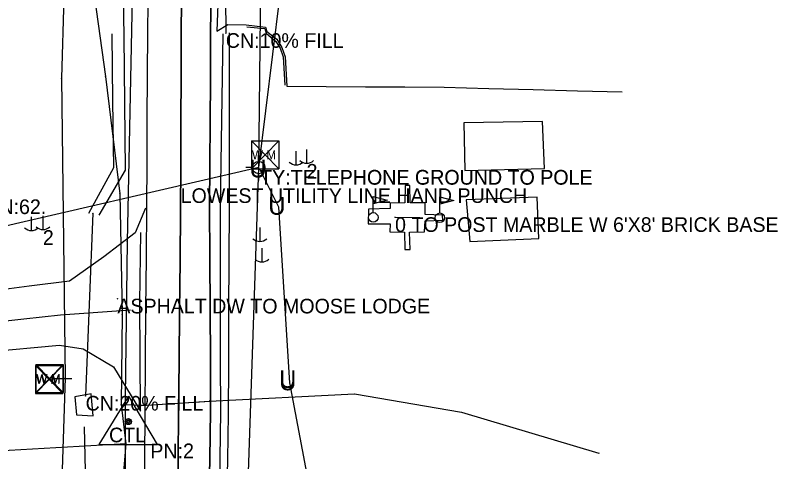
# Model space of a CAD drawing. Extents: x 1707085 to 1720058, y 548761 to 560063.
# Drawn here: x 1712426.8 to 1712686.7, y 550534.1 to 550686.5 of the extents above; entities that cross this region are included whole.
import ezdxf

# ---------------------------------------------------------------- set-up
doc = ezdxf.new("R2010")
doc.units = 0
for name, color, linetype in [('3', 7, 'Continuous'), ('44', 7, 'Continuous'), ('Default', 7, 'Continuous'), ('R_Contour Annot', 7, 'Continuous'), ('R_Horz Alg Annot', 7, 'Continuous'), ('R_Water Annot', 7, 'Continuous'), ('S_CURB', 7, 'Continuous'), ('S_DRG_PT_SYM', 7, 'Continuous'), ('S_DRIVEWAY', 7, 'Continuous'), ('S_EDGE_CONCRETE', 7, 'Continuous'), ('S_EDGE_PAVEMENT', 7, 'Continuous'), ('S_ELECTRIC_UTILITIES_ANNOT', 7, 'Continuous'), ('S_FLAG_POLE', 7, 'Continuous'), ('S_GAS_UTILITIES', 7, 'Continuous'), ('S_MSC_PT_SYM', 7, 'Continuous'), ('S_PAVEMENT_CROWN', 7, 'Continuous'), ('S_PRIMARY_CTL_ANNOT', 7, 'Continuous'), ('S_SIDE_DRAIN_ANNOT', 7, 'Continuous'), ('S_SIGN_ANNOT', 7, 'Continuous'), ('S_SURVEY_TEXT_ANNOT', 7, 'Continuous'), ('S_UNDERGROUND_CABLE', 7, 'Continuous'), ('S_UNDERGROUND_CABLE_ANNOT', 7, 'Continuous'), ('S_UTILITY_POLE', 7, 'Continuous'), ('S_UTILITY_POLE_ANNOT', 7, 'Continuous'), ('S_UTL_PT_SYM', 7, 'Continuous')]:
    doc.layers.add(name, color=color, linetype=linetype)

msp = doc.modelspace()

# ---------------------------------------------------------------- linework, layer by layer
for points in [[(1712463.94, 550855.4), (1712463.2, 550842.56), (1712462.46, 550829.72), (1712462.55, 550815.13), (1712462.64, 550800.54), (1712462.46, 550798.31), (1712462.44, 550791.97), (1712462.37, 550776.28), (1712462.3, 550760.58), (1712462.68, 550740.27), (1712463.06, 550719.96), (1712463.44, 550699.64), (1712463.81, 550679.33), (1712464.04, 550656.46), (1712464.27, 550633.6), (1712455.29, 550618.31)], [(1712499.77, 550680.44), (1712499.76, 550665.56), (1712499.74, 550650.67), (1712499.72, 550635.78), (1712499.71, 550620.89), (1712499.63, 550603.25), (1712499.55, 550585.61), (1712499.47, 550567.97), (1712499.4, 550550.32), (1712499.11, 550534.87), (1712498.82, 550519.41), (1712498.53, 550503.95), (1712498.24, 550488.49), (1712498.1, 550472.1), (1712497.96, 550455.71), (1712497.82, 550439.31), (1712497.69, 550422.92)], [(1712459.68, 550680.09), (1712459.99, 550657.24), (1712460.29, 550634.4), (1712451.79, 550618.84)], [(1712497.6, 550680.15), (1712497.36, 550665.48), (1712497.12, 550650.8), (1712496.87, 550636.13), (1712496.63, 550621.46), (1712496.66, 550603.89), (1712496.68, 550586.31), (1712496.71, 550568.74), (1712496.74, 550551.17), (1712496.57, 550535.35), (1712496.4, 550519.52), (1712496.23, 550503.7), (1712496.06, 550487.88), (1712496.27, 550471.69), (1712496.49, 550455.51), (1712496.71, 550439.33), (1712496.93, 550423.15)], [(1712450.26, 550546.06), (1712450.63, 550530.87), (1712451.01, 550515.67), (1712451.38, 550500.48), (1712451.76, 550485.28), (1712453.29, 550470.36), (1712454.82, 550455.43), (1712456.35, 550440.5), (1712457.89, 550425.57), (1712457.37, 550408.66), (1712456.85, 550391.74), (1712456.33, 550374.83), (1712455.82, 550357.92), (1712457.14, 550352.68), (1712454.4, 550340.57)]]:
    msp.add_lwpolyline(points)
msp.add_lwpolyline([(1712452.7, 550557.31), (1712447.08, 550556.32), (1712447.67, 550550.13), (1712453.36, 550549.82)], close=True)
at = {"layer": '3'}
for p, q in [((1712498.23, 550737.65), (1712498.59, 550680.34)), ((1712453.31, 550618.91), (1712450.79, 550556.58))]:
    msp.add_line(p, q, dxfattribs=at)
at = {"layer": '44'}
for p, q in [((1712468.97, 550809.65), (1712465.01, 550609.18)), ((1712465.01, 550609.18), (1712464.32, 550556.31)), ((1712464.32, 550556.31), (1712464.29, 550357.8))]:
    msp.add_line(p, q, dxfattribs=at)
at = {"layer": 'R_Contour Annot'}
for p, q in [((1712465.36, 550556.54), (1712455.33, 550540.02)), ((1712465.36, 550556.54), (1712475.19, 550540.02)), ((1712455.33, 550540.02), (1712475.19, 550540.02))]:
    msp.add_line(p, q, dxfattribs=at)
for radius in [1.04, 0.609, 0.344]:
    msp.add_circle((1712465.36, 550547.84), radius, dxfattribs=at)
at = {"layer": 'R_Horz Alg Annot'}
msp.add_line((1712556.28, 550617.54), (1712564.64, 550617.46), dxfattribs=at)
at = {"layer": 'R_Water Annot'}
for p, q in [((1712444.67, 550744.2), (1712442.63, 550664.98)), ((1712442.63, 550664.98), (1712443.82, 550562.74)), ((1712507.29, 550643.57), (1712516.63, 550643.57)), ((1712507.29, 550643.57), (1712507.29, 550634.08)), ((1712507.29, 550643.57), (1712516.63, 550634.08)), ((1712516.63, 550643.57), (1712507.29, 550634.08)), ((1712516.63, 550643.57), (1712516.63, 550634.08)), ((1712507.29, 550634.08), (1712516.63, 550634.08)), ((1712433.66, 550566.94), (1712443, 550566.94)), ((1712433.66, 550566.94), (1712433.66, 550557.45)), ((1712433.66, 550566.94), (1712443, 550557.45)), ((1712443, 550566.94), (1712433.66, 550557.45)), ((1712433.85, 550567.29), (1712443.19, 550567.29)), ((1712433.85, 550567.29), (1712433.85, 550557.79)), ((1712433.85, 550567.29), (1712443.19, 550557.79)), ((1712443.19, 550567.29), (1712433.85, 550557.79)), ((1712443, 550566.94), (1712443, 550557.45)), ((1712443.19, 550567.29), (1712443.19, 550557.79)), ((1712446.1, 550562.41), (1712439.34, 550562.47)), ((1712443.82, 550562.74), (1712442.13, 550508.33)), ((1712433.66, 550557.45), (1712443, 550557.45)), ((1712433.85, 550557.79), (1712443.19, 550557.79))]:
    msp.add_line(p, q, dxfattribs=at)
at = {"layer": 'S_CURB'}
msp.add_lwpolyline([(1712505.73, 550682.49), (1712511.84, 550681.96), (1712512.3, 550680.34), (1712515.58, 550677.49), (1712517.06, 550675.18), (1712518.1, 550672.22), (1712518.66, 550662.66)], dxfattribs=at)
at = {"layer": 'S_DRG_PT_SYM'}
for points in [[(1712498.59, 550680.34), (1712498.59, 550680.39), (1712498.59, 550680.34), (1712498.54, 550680.34), (1712498.59, 550680.34), (1712498.59, 550680.29), (1712498.59, 550680.34), (1712498.64, 550680.34)], [(1712453.31, 550618.91), (1712453.31, 550618.96), (1712453.31, 550618.91), (1712453.26, 550618.91), (1712453.31, 550618.91), (1712453.31, 550618.86), (1712453.31, 550618.91), (1712453.36, 550618.91)], [(1712450.79, 550556.58), (1712450.79, 550556.63), (1712450.79, 550556.58), (1712450.74, 550556.58), (1712450.79, 550556.58), (1712450.79, 550556.53), (1712450.79, 550556.58), (1712450.84, 550556.58)]]:
    msp.add_lwpolyline(points, dxfattribs=at)
at = {"layer": 'S_DRIVEWAY'}
msp.add_lwpolyline([(1712496.1, 550696.36), (1712495.51, 550681.07), (1712499.26, 550683.27), (1712505.5, 550683.16), (1712512.1, 550682.4), (1712512.62, 550680.93), (1712515.94, 550678.26), (1712517.66, 550675.48), (1712518.8, 550672.25), (1712519.38, 550662.3), (1712532.8, 550662.2), (1712546.21, 550662.09), (1712559.63, 550661.99), (1712573.04, 550661.89), (1712588.2, 550661.49), (1712603.36, 550661.09), (1712618.51, 550660.69), (1712633.67, 550660.29)], dxfattribs=at)
at = {"layer": 'S_EDGE_CONCRETE'}
for points in [[(1712606.51, 550650.18), (1712593.1, 550649.98), (1712579.68, 550649.78), (1712580.01, 550633.53), (1712593.6, 550633.84), (1712607.19, 550634.15)], [(1712572.51, 550616.5), (1712572.44, 550618.29), (1712566.54, 550618.47), (1712566.54, 550622.44), (1712561.41, 550622.48), (1712561.32, 550628.41), (1712559.67, 550628.42), (1712559.62, 550622.44), (1712554.59, 550622.31), (1712554.57, 550620.48), (1712547.23, 550620.33), (1712547.15, 550615.25), (1712554.58, 550615.35), (1712554.51, 550612.52), (1712559.51, 550612.4), (1712559.66, 550606.51), (1712561.46, 550606.52), (1712561.25, 550612.43), (1712566.33, 550612.58), (1712566.55, 550616.33)], [(1712604.69, 550624.38), (1712580.57, 550623.49), (1712581.8, 550609.23), (1712605.25, 550610.31)]]:
    msp.add_lwpolyline(points, close=True, dxfattribs=at)
at = {"layer": 'S_EDGE_PAVEMENT'}
for points in [[(1712495.13, 550823.13), (1712494.92, 550798.66), (1712494.59, 550779.89), (1712494.26, 550761.12), (1712494.05, 550740.6), (1712493.83, 550720.08), (1712493.62, 550699.57), (1712493.41, 550679.05), (1712493.32, 550664.55), (1712493.24, 550650.05), (1712493.16, 550635.55), (1712493.07, 550621.05), (1712493.15, 550603.63), (1712493.23, 550586.21), (1712493.31, 550568.79), (1712493.38, 550551.37), (1712493.12, 550535.16), (1712492.85, 550518.96), (1712492.58, 550502.75), (1712492.31, 550486.54), (1712492.24, 550470.74), (1712492.17, 550454.95), (1712492.11, 550439.15), (1712492.04, 550423.35)], [(1712472.07, 550700.51), (1712471.86, 550680.8), (1712471.78, 550665.91), (1712471.7, 550651.01), (1712471.62, 550636.12), (1712471.54, 550621.23), (1712471.39, 550603.69), (1712471.24, 550586.15), (1712471.09, 550568.61), (1712470.94, 550551.07), (1712470.87, 550534.75), (1712470.79, 550518.44), (1712470.72, 550502.12), (1712470.65, 550485.8), (1712470.61, 550470.5), (1712470.56, 550455.2), (1712470.52, 550439.9), (1712470.48, 550424.59)], [(1712492.04, 550423.35), (1712492.11, 550439.15), (1712492.17, 550454.95), (1712492.24, 550470.74), (1712492.31, 550486.54), (1712492.58, 550502.75), (1712492.85, 550518.96), (1712493.12, 550535.16), (1712493.38, 550551.37), (1712493.31, 550568.79), (1712493.23, 550586.21), (1712493.15, 550603.63), (1712493.07, 550621.05), (1712493.16, 550635.55), (1712493.24, 550650.05), (1712493.32, 550664.55), (1712493.41, 550679.05), (1712493.62, 550699.57)], [(1712471.17, 550620.67), (1712467.69, 550612.22), (1712457.04, 550604.08), (1712445.32, 550595.74), (1712431.55, 550593.99), (1712417.79, 550592.25), (1712404.03, 550590.5), (1712390.26, 550588.75), (1712376.07, 550587.54), (1712361.88, 550586.32), (1712347.69, 550585.11), (1712333.49, 550583.89), (1712318.99, 550582.43), (1712304.48, 550580.97), (1712289.98, 550579.51), (1712275.47, 550578.05), (1712261.19, 550576.58), (1712246.9, 550575.1), (1712232.62, 550573.62), (1712218.34, 550572.14), (1712202.94, 550570.5), (1712187.55, 550568.86), (1712172.16, 550567.21), (1712156.76, 550565.57)], [(1712258.21, 550556.53), (1712272.38, 550557.94), (1712286.94, 550559.4), (1712301.51, 550560.87), (1712316.07, 550562.33), (1712330.64, 550563.79), (1712346.08, 550565.18), (1712361.53, 550566.58), (1712376.97, 550567.98), (1712392.42, 550569.37), (1712417.15, 550571.61), (1712441.87, 550573.85), (1712449.92, 550572.7), (1712460.32, 550566.47), (1712469.46, 550551.37), (1712469.35, 550569.93), (1712469.23, 550588.5), (1712469.6, 550612.34)]]:
    msp.add_lwpolyline(points, dxfattribs=at)
at = {"layer": 'S_FLAG_POLE'}
for p, q in [((1712548.85, 550619.13), (1712548.85, 550624.67)), ((1712548.85, 550624.67), (1712553.61, 550623.39)), ((1712553.61, 550623.39), (1712548.85, 550622.11)), ((1712571.55, 550619), (1712571.55, 550624.54)), ((1712571.55, 550624.54), (1712576.32, 550623.26)), ((1712576.32, 550623.26), (1712571.55, 550621.98))]:
    msp.add_line(p, q, dxfattribs=at)
for centre in [(1712548.85, 550617.5), (1712571.55, 550617.37)]:
    msp.add_circle(centre, 1.63, dxfattribs=at)
at = {"layer": 'S_GAS_UTILITIES'}
for p, q in [((1712452.58, 550701.34), (1712457.58, 550665.61)), ((1712457.58, 550665.61), (1712462.44, 550625.57)), ((1712462.44, 550625.57), (1712463.3, 550584.46)), ((1712463.3, 550584.46), (1712462.86, 550553.68)), ((1712493.01, 550554.75), (1712542.49, 550557.29)), ((1712542.49, 550557.29), (1712578.94, 550551.03)), ((1712462.86, 550553.68), (1712464.54, 550540.21)), ((1712462.86, 550553.68), (1712471.48, 550553.48)), ((1712469.7, 550553.3), (1712493.2, 550554.79)), ((1712471.48, 550553.48), (1712493.01, 550554.75)), ((1712578.94, 550551.03), (1712625.79, 550537.1)), ((1712464.54, 550540.21), (1712419.89, 550537.7)), ((1712464.54, 550540.21), (1712459.44, 550482.79))]:
    msp.add_line(p, q, dxfattribs=at)
at = {"layer": 'S_MSC_PT_SYM'}
for points in [[(1712556.28, 550617.54), (1712556.28, 550617.59), (1712556.28, 550617.54), (1712556.23, 550617.54), (1712556.28, 550617.54), (1712556.28, 550617.49), (1712556.28, 550617.54), (1712556.33, 550617.54)], [(1712564.64, 550617.46), (1712564.64, 550617.51), (1712564.64, 550617.46), (1712564.59, 550617.46), (1712564.64, 550617.46), (1712564.64, 550617.41), (1712564.64, 550617.46), (1712564.69, 550617.46)], [(1712461.61, 550589.73), (1712461.61, 550589.78), (1712461.61, 550589.73), (1712461.56, 550589.73), (1712461.61, 550589.73), (1712461.61, 550589.68), (1712461.61, 550589.73), (1712461.66, 550589.73)]]:
    msp.add_lwpolyline(points, dxfattribs=at)
at = {"layer": 'S_PAVEMENT_CROWN'}
for points in [[(1712481.54, 550423.86), (1712481.65, 550439.32), (1712481.75, 550454.78), (1712481.85, 550470.24), (1712481.96, 550485.7), (1712482.09, 550502.11), (1712482.23, 550518.51), (1712482.37, 550534.91), (1712482.5, 550551.32), (1712482.66, 550568.44), (1712482.82, 550585.57), (1712482.97, 550602.7), (1712483.13, 550619.83), (1712483.2, 550635.1), (1712483.27, 550650.38), (1712483.33, 550665.65), (1712483.4, 550680.93), (1712483.56, 550700.86)], [(1712483.56, 550700.86), (1712483.4, 550680.93), (1712483.33, 550665.65), (1712483.27, 550650.38), (1712483.2, 550635.1), (1712483.13, 550619.83), (1712482.97, 550602.7), (1712482.82, 550585.57), (1712482.66, 550568.44), (1712482.5, 550551.32), (1712482.37, 550534.91), (1712482.23, 550518.51), (1712482.09, 550502.11), (1712481.96, 550485.7), (1712481.85, 550470.24), (1712481.75, 550454.78), (1712481.65, 550439.32), (1712481.54, 550423.86)], [(1712158.89, 550555.88), (1712173.76, 550557.46), (1712188.62, 550559.04), (1712203.49, 550560.63), (1712218.36, 550562.21), (1712232.94, 550563.66), (1712247.53, 550565.11), (1712262.11, 550566.56), (1712276.7, 550568.01), (1712291.01, 550569.42), (1712305.32, 550570.83), (1712319.63, 550572.24), (1712333.93, 550573.64), (1712348.47, 550574.94), (1712363.01, 550576.24), (1712377.55, 550577.54), (1712392.09, 550578.84), (1712404.64, 550580.19), (1712417.19, 550581.55), (1712429.74, 550582.9), (1712442.29, 550584.25), (1712466.13, 550585.96)]]:
    msp.add_lwpolyline(points, dxfattribs=at)
at = {"layer": 'S_UNDERGROUND_CABLE'}
for p, q in [((1712516.69, 550620.96), (1712510.27, 550633.69)), ((1712520.43, 550561.06), (1712516.69, 550620.96)), ((1712530.81, 550505.98), (1712520.43, 550561.06))]:
    msp.add_line(p, q, dxfattribs=at)
at = {"layer": 'S_UTILITY_POLE'}
for p, q in [((1712509.79, 550634.49), (1712523.09, 550740.94)), ((1712509.78, 550636.6), (1712509.78, 550638.85)), ((1712522.49, 550640.12), (1712522.49, 550635.4)), ((1712526.1, 550640.65), (1712526.1, 550635.93)), ((1712507.69, 550634.47), (1712505.37, 550634.47)), ((1712509.86, 550630.05), (1712509.86, 550632.38)), ((1712436.21, 550618.07), (1712436.21, 550613.35)), ((1712432.26, 550617.73), (1712432.26, 550613)), ((1712510.13, 550614), (1712510.13, 550609.28)), ((1712510.83, 550607.01), (1712510.83, 550602.28))]:
    msp.add_line(p, q, dxfattribs=at)
for points in [[(1712497.7, 549518.48), (1712500.91, 549949.57), (1712500.58, 550149.34), (1712502.49, 550416.34), (1712509.79, 550634.49), (1712512.76, 550903.53), (1712513.37, 551033.49), (1712513.87, 551133.13), (1712444.45, 551132.54)], [(1712509.79, 550634.49), (1712409.58, 550611.31), (1712256.35, 550594.36), (1711944.09, 550562.38)]]:
    msp.add_lwpolyline(points, dxfattribs=at)
msp.add_circle((1712509.79, 550634.49), 2.13, dxfattribs=at)
for centre in [(1712522.56, 550638.82), (1712526.16, 550639.35), (1712432.32, 550616.42), (1712436.27, 550616.77), (1712510.19, 550612.7), (1712510.89, 550605.7)]:
    msp.add_arc(centre, 3.41, 226.3972, 313.6028, dxfattribs=at)
at = {"layer": 'S_UTL_PT_SYM'}
for points in [[(1712442.63, 550664.98), (1712442.63, 550665.03), (1712442.63, 550664.98), (1712442.58, 550664.98), (1712442.63, 550664.98), (1712442.63, 550664.93), (1712442.63, 550664.98), (1712442.68, 550664.98)], [(1712457.58, 550665.61), (1712457.58, 550665.66), (1712457.58, 550665.61), (1712457.53, 550665.61), (1712457.58, 550665.61), (1712457.58, 550665.56), (1712457.58, 550665.61), (1712457.63, 550665.61)], [(1712483.18, 550627.42), (1712483.18, 550627.47), (1712483.18, 550627.42), (1712483.13, 550627.42), (1712483.18, 550627.42), (1712483.18, 550627.37), (1712483.18, 550627.42), (1712483.23, 550627.42)], [(1712462.44, 550625.57), (1712462.44, 550625.62), (1712462.44, 550625.57), (1712462.39, 550625.57), (1712462.44, 550625.57), (1712462.44, 550625.52), (1712462.44, 550625.57), (1712462.49, 550625.57)], [(1712465.01, 550609.18), (1712465.01, 550609.23), (1712465.01, 550609.18), (1712464.95, 550609.18), (1712465.01, 550609.18), (1712465.01, 550609.13), (1712465.01, 550609.18), (1712465.05, 550609.18)], [(1712463.3, 550584.46), (1712463.3, 550584.51), (1712463.3, 550584.46), (1712463.25, 550584.46), (1712463.3, 550584.46), (1712463.3, 550584.41), (1712463.3, 550584.46), (1712463.35, 550584.46)], [(1712443.82, 550562.74), (1712443.82, 550562.79), (1712443.82, 550562.74), (1712443.77, 550562.74), (1712443.82, 550562.74), (1712443.82, 550562.69), (1712443.82, 550562.74), (1712443.87, 550562.74)], [(1712464.32, 550556.31), (1712464.32, 550556.36), (1712464.32, 550556.31), (1712464.28, 550556.31), (1712464.32, 550556.31), (1712464.32, 550556.26), (1712464.32, 550556.31), (1712464.38, 550556.31)], [(1712542.49, 550557.29), (1712542.49, 550557.34), (1712542.49, 550557.29), (1712542.44, 550557.29), (1712542.49, 550557.29), (1712542.49, 550557.24), (1712542.49, 550557.29), (1712542.54, 550557.29)], [(1712462.86, 550553.68), (1712462.86, 550553.73), (1712462.86, 550553.68), (1712462.81, 550553.68), (1712462.86, 550553.68), (1712462.86, 550553.63), (1712462.86, 550553.68), (1712462.91, 550553.68)], [(1712462.86, 550553.68), (1712462.86, 550553.73), (1712462.86, 550553.68), (1712462.81, 550553.68), (1712462.86, 550553.68), (1712462.86, 550553.63), (1712462.86, 550553.68), (1712462.91, 550553.68)], [(1712469.7, 550553.3), (1712469.7, 550553.35), (1712469.7, 550553.3), (1712469.65, 550553.3), (1712469.7, 550553.3), (1712469.7, 550553.25), (1712469.7, 550553.3), (1712469.75, 550553.3)], [(1712471.48, 550553.48), (1712471.48, 550553.53), (1712471.48, 550553.48), (1712471.43, 550553.48), (1712471.48, 550553.48), (1712471.48, 550553.43), (1712471.48, 550553.48), (1712471.53, 550553.48)], [(1712493.01, 550554.75), (1712493.01, 550554.8), (1712493.01, 550554.75), (1712492.96, 550554.75), (1712493.01, 550554.75), (1712493.01, 550554.7), (1712493.01, 550554.75), (1712493.06, 550554.75)], [(1712493.2, 550554.79), (1712493.2, 550554.84), (1712493.2, 550554.79), (1712493.15, 550554.79), (1712493.2, 550554.79), (1712493.2, 550554.74), (1712493.2, 550554.79), (1712493.25, 550554.79)], [(1712578.94, 550551.03), (1712578.94, 550551.08), (1712578.94, 550551.03), (1712578.89, 550551.03), (1712578.94, 550551.03), (1712578.94, 550550.98), (1712578.94, 550551.03), (1712578.99, 550551.03)], [(1712464.54, 550540.21), (1712464.54, 550540.26), (1712464.54, 550540.21), (1712464.48, 550540.21), (1712464.54, 550540.21), (1712464.54, 550540.16), (1712464.54, 550540.21), (1712464.58, 550540.21)], [(1712464.54, 550540.21), (1712464.54, 550540.26), (1712464.54, 550540.21), (1712464.48, 550540.21), (1712464.54, 550540.21), (1712464.54, 550540.16), (1712464.54, 550540.21), (1712464.58, 550540.21)], [(1712625.79, 550537.1), (1712625.79, 550537.15), (1712625.79, 550537.1), (1712625.74, 550537.1), (1712625.79, 550537.1), (1712625.79, 550537.05), (1712625.79, 550537.1), (1712625.84, 550537.1)]]:
    msp.add_lwpolyline(points, dxfattribs=at)

# ---------------------------------------------------------------- texts
at = {"layer": 'Default'}
for p in [(1712506.64, 550631.15), (1712506.69, 550631.1), (1712513.06, 550618.41), (1712513.13, 550618.39), (1712516.79, 550559.33), (1712516.8, 550558.51)]:
    msp.add_text('U', height=6, rotation=360, dxfattribs=at).set_placement(p)
at = {"layer": 'R_Contour Annot'}
msp.add_text('CTL', height=5, rotation=360, dxfattribs=at).set_placement((1712458.78, 550540.76))
at = {"layer": 'R_Water Annot'}
for p in [(1712507.49, 550637.33), (1712433.87, 550560.71), (1712434.06, 550561.05)]:
    msp.add_text('W M', height=3, rotation=360, dxfattribs=at).set_placement(p)
at = {"layer": 'S_ELECTRIC_UTILITIES_ANNOT'}
msp.add_text('LOWEST UTILITY LINE HAND PUNCH', height=5, dxfattribs=at).set_placement((1712483.18, 550622.42))
at = {"layer": 'S_PRIMARY_CTL_ANNOT'}
msp.add_text('PN:2', height=5, dxfattribs=at).set_placement((1712472.86, 550535.34))
at = {"layer": 'S_SIDE_DRAIN_ANNOT'}
for s, p in [('CN:10% FILL', (1712498.59, 550675.34)), ('DI:36" TY:RCP CN:5% FILL LN:62.', (1712332.82, 550618.63)), ('CN:20% FILL', (1712450.79, 550551.58))]:
    msp.add_text(s, height=5, dxfattribs=at).set_placement(p)
at = {"layer": 'S_SIGN_ANNOT'}
msp.add_text("0 TO POST MARBLE W 6'X8' BRICK BASE", height=5, dxfattribs=at).set_placement((1712556.28, 550612.54))
at = {"layer": 'S_SURVEY_TEXT_ANNOT'}
msp.add_text('ASPHALT DW TO MOOSE LODGE', height=5, dxfattribs=at).set_placement((1712461.61, 550584.73))
at = {"layer": 'S_UNDERGROUND_CABLE_ANNOT'}
for p in [(1712510.27, 550628.69), (1712510.32, 550628.65)]:
    msp.add_text('TY:TELEPHONE GROUND TO POLE', height=5, dxfattribs=at).set_placement(p)
at = {"layer": 'S_UTILITY_POLE_ANNOT'}
for p in [(1712526.11, 550630.71), (1712436.22, 550608.13)]:
    msp.add_text('2', height=5, dxfattribs=at).set_placement(p)

doc.saveas('drawing.dxf')
